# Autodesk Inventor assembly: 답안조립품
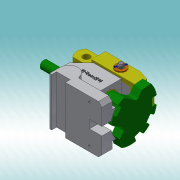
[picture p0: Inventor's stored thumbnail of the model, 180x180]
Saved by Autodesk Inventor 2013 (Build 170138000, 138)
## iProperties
Created: 2016-11
Part Number: 답안조립품
Document SubType Name: Assembly
Designer: dgall
Author: dgall
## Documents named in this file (8)
- C:\Users\dgall\Desktop\461107V1001\답안조립품.iam
- C:\Users\dgall\Desktop\461107V1001\본체.ipt
- C:\Users\dgall\Desktop\461107V1001\부시.ipt
- C:\Users\dgall\Desktop\461107V1001\분할대.ipt
- C:\Users\dgall\Desktop\461107V1001\분할축.ipt
- C:\Users\dgall\Desktop\461107V1001\와셔.ipt
- C:\Users\dgall\Desktop\461107V1001\원통형핀.ipt
- C:\Users\dgall\Desktop\461107V1001\클레비스핀.ipt
